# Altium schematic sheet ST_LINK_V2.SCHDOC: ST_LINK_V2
size A4; DocumentNumber: 2; Revision: D.1(PCB.SCH); SheetNumber: 4; SheetTotal: 5
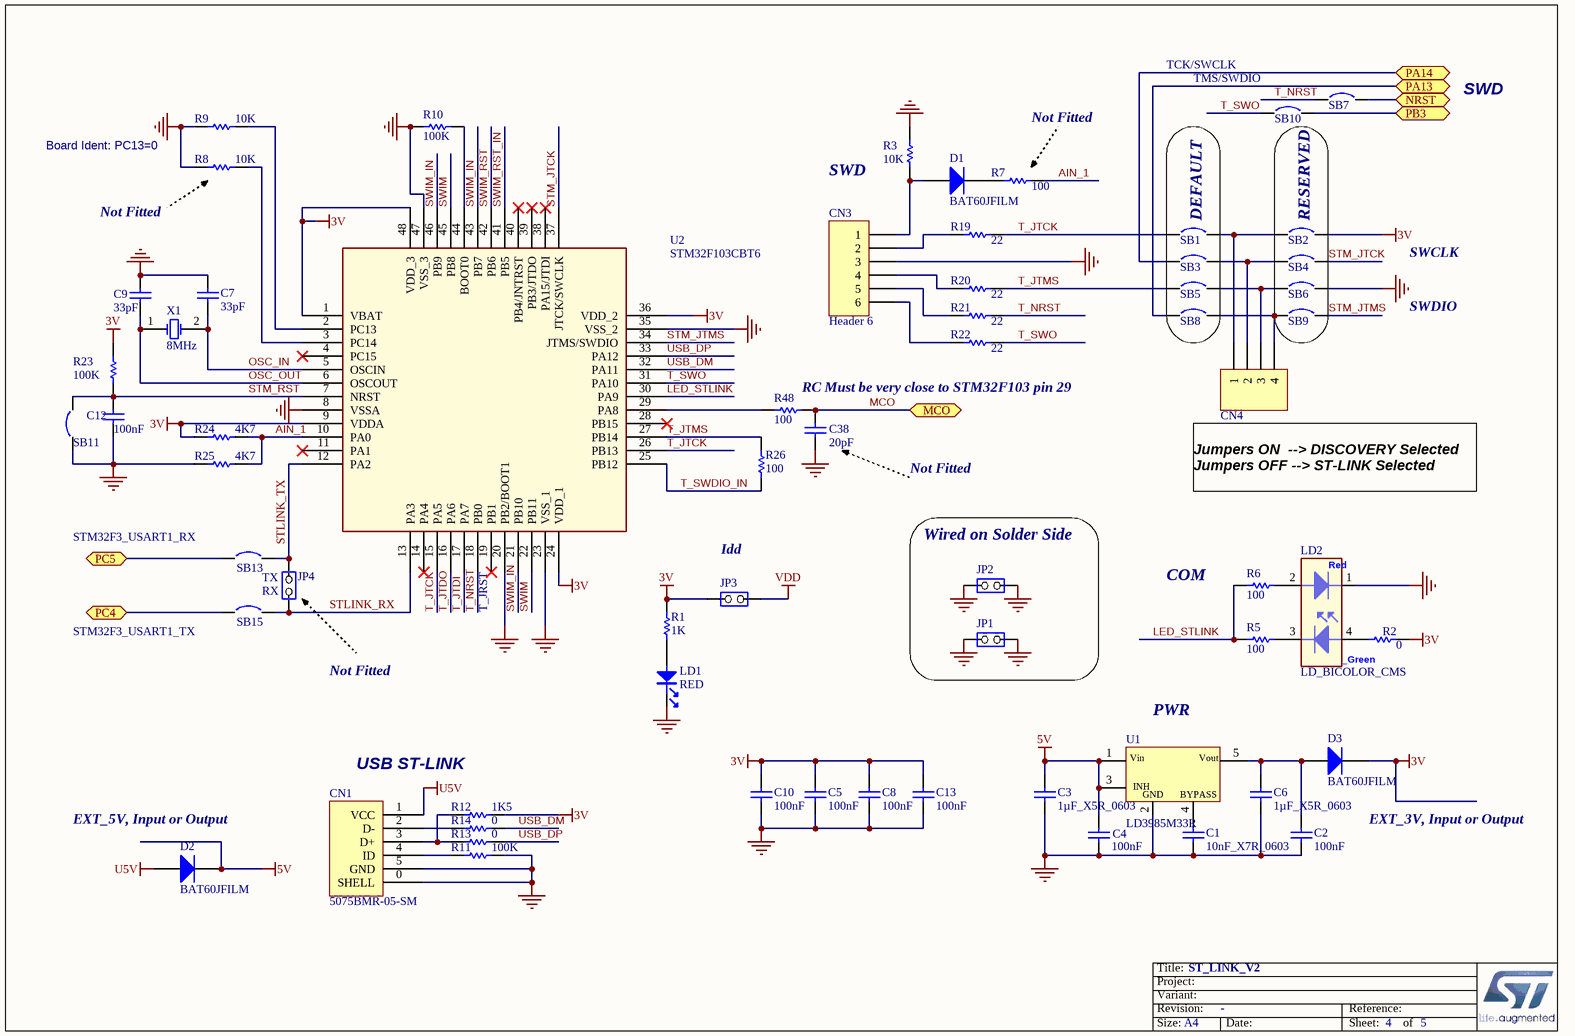
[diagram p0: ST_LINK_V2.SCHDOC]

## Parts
C1  10nF_X7R_0603  [0603C]
C2  100nF  [0603C]
C3  1µF_X5R_0603  [0603C]
C4  100nF  [0603C]
C5  100nF  [0402C]
C6  1µF_X5R_0603  [0603C]
C7  33pF  [0402C]
C8  100nF  [0402C]
C9  33pF  [0402C]
C10  100nF  [0402C]
C12  100nF  [0402C]
C13  100nF  [0402C]
C38  20pF  [0402C]
CN1  5075BMR-05-SM  [USB-MINI-B-SMD]
CN3  Header 6  [HDR1X6]
CN4  Header 4  [Header 4]  (value not drawn)
D1  BAT60JFILM  [SOD323/A]
D2  BAT60JFILM  [SOD323/A]
D3  BAT60JFILM  [SOD323/A]
JP1  (no value)  [SIP2/2.54]
JP2  (no value)  [SIP2/2.54]
JP3  (no value)  [SIP2/2.54]
JP4  JP2  [SIP2/2.54]  (value not drawn)
LD1  RED  [0603D]
LD2  LD_BICOLOR_CMS  [HSMF-A201]
R1  1K  [0402R]
R2  0  [0402R]
R3  10K  [0402R]
R5  100  [0402R]
R6  100  [0402R]
R7  100  [0402R]
R8  10K  [0402R]
R9  10K  [0402R]
R10  100K  [0402R]
R11  100K  [0402R]
R12  1K5  [0402R]
R13  0  [0402R]
R14  0  [0402R]
R19  22  [0402R]
R20  22  [0402R]
R21  22  [0402R]
R22  22  [0402R]
R23  100K  [0402R]
R24  4K7  [0402R]
R25  4K7  [0402R]
R26  100  [0402R]
R48  100  [0402R]
SB1  Circuit Breaker  [JP2_SMD]  (value not drawn)
SB2  Circuit Breaker  [JP2_SMD]  (value not drawn)
SB3  Circuit Breaker  [JP2_SMD]  (value not drawn)
SB4  Circuit Breaker  [JP2_SMD]  (value not drawn)
SB5  Circuit Breaker  [JP2_SMD]  (value not drawn)
SB6  Circuit Breaker  [JP2_SMD]  (value not drawn)
SB7  Circuit Breaker  [JP2_SMD]  (value not drawn)
SB8  Circuit Breaker  [JP2_SMD]  (value not drawn)
SB9  Circuit Breaker  [JP2_SMD]  (value not drawn)
SB10  Circuit Breaker  [JP2_SMD]  (value not drawn)
SB11  Circuit Breaker  [JP2_SMD]  (value not drawn)
SB13  Circuit Breaker  [JP2_SMD]  (value not drawn)
SB15  Circuit Breaker  [JP2_SMD]  (value not drawn)
U1  LD3985M33R  [SOT-23-5L]
U2  STM32F103CBT6  [ICC_LQFP48_7X7_P050]
X1  8MHz  [XTAL1]

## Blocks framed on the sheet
DEFAULT: SB1 SB3 SB5 SB8
RESERVED: SB2 SB4 SB6 SB9
Wired on Solder Side: JP1 JP2

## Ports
MCO, NRST, PA13, PA14, PB3, PC4, PC5

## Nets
3V: C5.2 C8.1 C10.2 C13.2 D3.2(K) JP3.1(COMMON) R1.2 R2.2 R12.2 R23.2 R24.1 SB2.2 U2.1(VBAT) U2.9(VDDA) U2.24(VDD_1) U2.36(VDD_2) U2.48(VDD_3)
5V: C3.2 C4.2 D2.2(K) U1.1(Vin) U1.3(CE)
GND: C1.1 C2.1 C3.1 C4.1 C5.1 C6.2 C7.1 C8.2 C9.1 C10.1 C12.1 C13.1 C38.2 CN1.0(SHELL) CN1.5(GND) CN3.3 JP1.1(COMMON) JP1.2(NO) JP2.1(COMMON) JP2.2(NO) LD1.2 LD2.1 R3.2 R8.1 R9.1 R10.1 R11.2 R25.1 SB6.2 SB11.1 U1.2(GND) U2.8(VSSA) U2.20(PB2/BOOT1) U2.23(VSS_1) U2.35(VSS_2) U2.47(VSS_3)
U5V: CN1.1(VCC) D2.1(A)
VDD: JP3.2(NO)
AIN_1: R7.2 R24.2 R25.2 U2.10(PA0)
LED_STLINK: R5.1 R6.1 U2.30(PA9)
MCO: C38.1 R48.2 ; port MCO
NRST: SB7.2 ; port NRST
OSC_IN: C7.2 U2.5(OSCIN) X1.2(OSC2)
OSC_OUT: C9.2 U2.6(OSCOUT) X1.1(OSC1)
PA13: SB8.1 ; port PA13
PA14: SB3.1 ; port PA14
PB3: SB10.2 ; port PB3
PC4: SB15.1 ; port PC4
PC5: SB13.1 ; port PC5
STLINK_RX: JP4.1(COMMON) SB15.2 U2.13(PA3)
STLINK_TX: JP4.2(NO) SB13.2 U2.12(PA2)
STM_JTCK: SB4.2 U2.37(JTCK/SWCLK)
STM_JTMS: SB9.2 U2.34(JTMS/SWDIO)
STM_RST: C12.2 R23.1 SB11.2 U2.7(NRST)
SWIM: U2.22(PB11) U2.45(PB8)
SWIM_IN: U2.21(PB10) U2.43(PB7) U2.46(PB9)
SWIM_RST: U2.42(PB6)
SWIM_RST_IN: U2.41(PB5)
T_JTCK: R19.2 SB1.1 U2.15(PA5) U2.26(PB13)
T_JTDI: U2.17(PA7)
T_JTDO: U2.16(PA6)
T_JTMS: R20.2 R26.2 SB5.1 U2.27(PB14)
T_NRST: R21.2 SB7.1 U2.18(PB0)
T_SWDIO_IN: R26.1 U2.25(PB12)
T_SWO: R22.2 SB10.1 U2.31(PA10)
USB_DM: R14.2 U2.32(PA11)
USB_DP: R13.2 U2.33(PA12)
NetC1_2: C1.2 U1.4(BYPASS)
NetC2_2: C2.2 C6.1 D3.1(A) U1.5(Vout)
NetCN1_2: CN1.2(D-) R14.1
NetCN1_3: CN1.3(D+) R12.1 R13.1
NetCN1_4: CN1.4(ID) R11.1
NetCN3_1: CN3.1 D1.1(A) R3.1
NetCN3_2: CN3.2 R19.1
NetCN3_4: CN3.4 R20.1
NetCN3_5: CN3.5 R21.1
NetCN3_6: CN3.6 R22.1
NetCN4_1: CN4.1 SB1.2 SB2.1
NetCN4_2: CN4.2 SB3.2 SB4.1
NetCN4_3: CN4.3 SB5.2 SB6.1
NetCN4_4: CN4.4 SB8.2 SB9.1
NetD1_2: D1.2(K) R7.1
NetLD1_1: LD1.1 R1.1
NetLD2_2: LD2.2 R6.2
NetLD2_3: LD2.3 R5.2
NetLD2_4: LD2.4 R2.1
NetR8_2: R8.2 U2.3(PC14)
NetR9_2: R9.2 U2.2(PC13)
NetR10_2: R10.2 U2.44(BOOT0)
NetR48_1: R48.1 U2.29(PA8)

Not connected (* = marked no-connect by the designer): U2 4(PC15)* 11(PA1)* 14(PA4)* 19(PB1)* 28(PB15)* 38(PA15/JTDI)* 39(PB3/JTDO)* 40(PB4/JNTRST)*

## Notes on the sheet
- TCK/SWCLK
- (near SB10) TMS/SWDIO
- SWD
- Board Ident: PC13=0
- Not Fitted
- SWCLK
- SWDIO
- (near R48) RC Must be very close to STM32F103 pin 29
- Jumpers ON  --> DISCOVERY Selected
  Jumpers OFF --> ST-LINK Selected
- STM32F3_USART1_RX
- TX
- (near JP3) Idd
- COM
- STM32F3_USART1_TX
- RX
- (near U2) T_JRST
- (near U1) PWR
- USB ST-LINK
- (near D2) EXT_5V, Input or Output
- EXT_3V, Input or Output

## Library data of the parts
C1 = CAP SMD 0603  X7R 10000PF 50V 10%: 0603  X7R 10NF; Order code RS: 2040779; Rated voltage: 50V; Tolerance: 10%
C2 C4 C5 C8 C10 C12 C13 = Cap: Capacitor
C3 C6 = CAP SMD 0603  X5R 1µF 25V 10%: 0603  X5R 1µF; Rated voltage: 25V; Tolerance: 10%
C7 C9 = Cap: Capacitor; Value: 20pF
C38 = Cap: Capacitor; Fitted: NO
CN1 = USB-MINI-typeB connector
CN3 = Header 6: Header, 6-Pin
CN4 = Header 4: Header, 4-Pin
D1-D3 = BAT60JFILM: Manuf_1: STM; Code - JEDEC: DO-214-AB; Provided: ST
JP1-JP3 = JP2
JP4 = JP2: Fitted: NO
LD1 = PHOTO
LD2 = LD_BICOLOR_CMS: Bicolor Led; Manuf_Part_1: HSMF-A201-A00J1; Manuf_1: Avago Technologies; Ref St: xxxxxx; cap_dec: ----
R1-R3 R5 R6 R9-R12 R19-R26 R48 = res1: Resistor
R7 R8 = res1: Resistor; Fitted: NO
R13 R14 = res1: Resistor; Value: 1K5
SB1 SB3 SB5 SB8 SB10 SB11 = Circuit Breaker: Solder: NO
SB2 SB4 SB6 SB7 SB9 = Circuit Breaker: Solder: YES
U1 = LD3985M33R: Ultra low drop-low noise BiCMOS voltage, regulators low ESR capacitors compatible; Manuf_1: STM; Provided: ST; Ref St: 9176161
U2 = STM32F103CBT6: Medium-density performance line ARM-based 32-bit MCU with 128KB Flash; Manuf_1: STM; Ref St: xxxxxxxx; Provided: ST; ECCN_US/EU: 3A991A2/NEC
X1 = XTAL: Crystal Oscillator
